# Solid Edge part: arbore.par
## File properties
Author: ion
Template: Iso Part.par
Last saved by: ion
Revision: 1
Application: Solid Edge
Accuracy: 0,990
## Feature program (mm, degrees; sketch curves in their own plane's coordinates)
sketch for "unnamed Protrusion 1" plane through (0, 0, 0) normal (0, -1, 0) x-axis (1, 0, 0)
  circle centre (0, 0) radius 5
extrude "unnamed Protrusion 1" add finite 60 along -normal
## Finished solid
Body 1: solid body, 3 faces, 2 edges, 0 vertices.
  Faces by surface: plane 2, cylinder 1
  Edges by curve: circle 2
Bounding box of the edges (mm): 10.000 x 60.000 x 10.000, from (-5, 0, -5) to (5, 60, 5).
Cylindrical faces by radius (mm): R5 x1
Planar faces by outward normal: +y 1, -y 1
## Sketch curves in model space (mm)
circle centre (0, 0, 0) radius 5
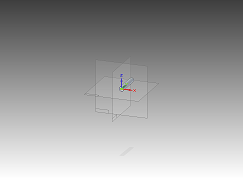
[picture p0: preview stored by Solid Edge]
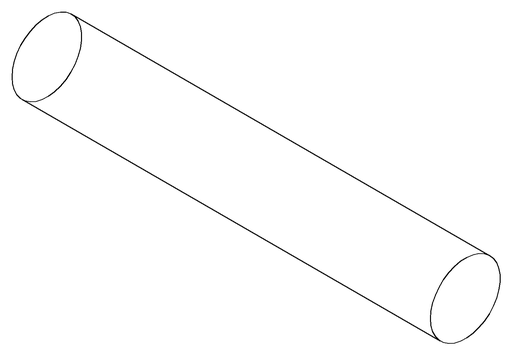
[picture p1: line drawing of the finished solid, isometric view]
